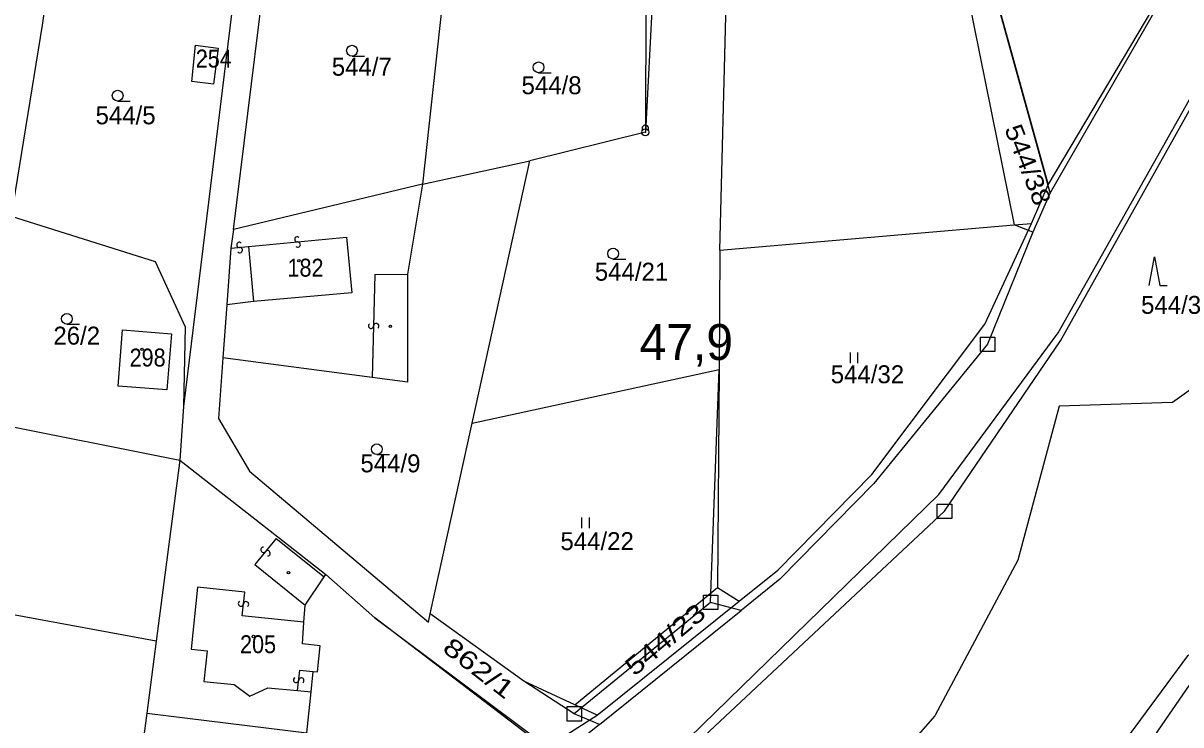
# Model space of a CAD drawing. Extents: x -680102 to -677253, y -1007548 to -1006096.
# Drawn here: x -679602.9 to -679441.7, y -1007197.5 to -1007099.8 of the extents above; entities that cross this region are included whole.
import ezdxf

# ---------------------------------------------------------------- set-up
doc = ezdxf.new("R2010")
doc.units = 0
for name, color, linetype, lineweight in [('1', 7, 'Continuous', 25), ('11', 7, 'Continuous', 25), ('24', 7, 'Continuous', 25), ('25', 7, 'Continuous', 25), ('35', 7, 'Continuous', 25), ('4', 7, 'Continuous', 25)]:
    doc.layers.add(name, color=color, linetype=linetype, lineweight=lineweight)
for name, color, linetype in [('18', 7, 'Continuous'), ('19', 7, 'Continuous'), ('56', 7, 'Continuous')]:
    doc.layers.add(name, color=color, linetype=linetype)

msp = doc.modelspace()

# ---------------------------------------------------------------- linework, layer by layer
at = {"layer": '1'}
for p, q in [((-679481.69, -1007044.65), (-679460.12, -1007122.3)), ((-679480.26, -1007051.71), (-679464.89, -1007127.87)), ((-679513.91, -1007069.87), (-679516.26, -1007114.97)), ((-679573.64, -1007128.49), (-679567.53, -1007078.91)), ((-679598.74, -1007089.06), (-679600.32, -1007100.05)), ((-679516.18, -1007095.82), (-679516.26, -1007114.97)), ((-679516.26, -1007114.97), (-679532.37, -1007118.94)), ((-679547.29, -1007122.2), (-679573.64, -1007128.49)), ((-679547.29, -1007122.2), (-679549.42, -1007134.75)), ((-679462.47, -1007127.66), (-679460.12, -1007122.3)), ((-679505.88, -1007131.4), (-679464.89, -1007127.87)), ((-679468.98, -1007141.69), (-679462.47, -1007127.66)), ((-679464.89, -1007127.87), (-679462.47, -1007127.66)), ((-679573.64, -1007128.49), (-679574.02, -1007131.12)), ((-679549.42, -1007134.75), (-679549.42, -1007149.76)), ((-679575.13, -1007146.4), (-679575.75, -1007154.83)), ((-679554.3, -1007149.14), (-679575.13, -1007146.4)), ((-679540.4, -1007155.5), (-679505.99, -1007148.01)), ((-679549.42, -1007149.76), (-679554.3, -1007149.14)), ((-679580.62, -1007153.16), (-679581.1, -1007160.64)), ((-679581.1, -1007160.64), (-679584.41, -1007185.88)), ((-679513.88, -1007202.94), (-679475.39, -1007165.44)), ((-679526.07, -1007194.74), (-679506.19, -1007178.41)), ((-679506.19, -1007178.41), (-679503.21, -1007180.3)), ((-679563.84, -1007183.24), (-679563.68, -1007180.84)), ((-679553.95, -1007182.63), (-679529.88, -1007200.6)), ((-679546.49, -1007183.2), (-679546.24, -1007182.06)), ((-679533.18, -1007191.45), (-679546.24, -1007182.06)), ((-679564.03, -1007186.25), (-679563.84, -1007183.24)), ((-679562.84, -1007192.91), (-679562.55, -1007190.09)), ((-679563.43, -1007198.62), (-679562.84, -1007192.91)), ((-679585.73, -1007195.92), (-679563.43, -1007198.62)), ((-679529.88, -1007200.6), (-679522.98, -1007196.16)), ((-679475.92, -1007196.29), (-679485.49, -1007207.11))]:
    msp.add_line(p, q, dxfattribs=at)
for points in [[(-679475.39, -1007165.44), (-679458.72, -1007142.92), (-679428.63, -1007089.4), (-679414.61, -1007067.19), (-679392.8, -1007041.16), (-679383.74, -1007034.41), (-679364.39, -1007022.5), (-679354.81, -1007027.12), (-679350.01, -1007026.23)], [(-679281.81, -1007027.69), (-679288.12, -1007026.06), (-679300.13, -1007025.55), (-679317.23, -1007033.9), (-679328.22, -1007036.44), (-679338.3, -1007036.24), (-679352.63, -1007045.79), (-679380.01, -1007071.86), (-679387.43, -1007092.29), (-679392.71, -1007125.35), (-679397.19, -1007140.32), (-679410.92, -1007159.43), (-679421.1, -1007177.36), (-679440.73, -1007187.9), (-679453.05, -1007204.6)], [(-679392.8, -1007041.16), (-679411.69, -1007075.81), (-679414.58, -1007097.41), (-679422.73, -1007127.1), (-679431.91, -1007144.79), (-679442.79, -1007152.62), (-679458.6, -1007153.13), (-679464.38, -1007174.57), (-679475.92, -1007196.29)], [(-679460.12, -1007122.3), (-679434.03, -1007078.35), (-679414.32, -1007049.92)], [(-679505.88, -1007131.4), (-679504.18, -1007064.29), (-679504.16, -1007063.4)], [(-679598.74, -1007089.06), (-679586.13, -1007086.43), (-679571.74, -1007080.61), (-679580.62, -1007153.16)], [(-679544.6, -1007097.51), (-679547.29, -1007122.2), (-679532.37, -1007118.94)], [(-679600.32, -1007100.05), (-679604.63, -1007126.67), (-679584.56, -1007132.96)], [(-679546.24, -1007182.06), (-679540.4, -1007155.5), (-679532.37, -1007118.94)], [(-679574.02, -1007131.12), (-679574.59, -1007139.02), (-679575.13, -1007146.4)], [(-679584.56, -1007132.96), (-679580.37, -1007142.08), (-679580.62, -1007153.16)], [(-679505.88, -1007131.4), (-679505.99, -1007148.01), (-679506.19, -1007178.41)], [(-679497.82, -1007175.98), (-679484.69, -1007162.65), (-679468.98, -1007141.69)], [(-679625.08, -1007151.88), (-679607.2, -1007155.44), (-679581.1, -1007160.64)], [(-679575.75, -1007154.83), (-679571.4, -1007162.2), (-679546.49, -1007183.2)], [(-679581.1, -1007160.64), (-679567.45, -1007171.33), (-679560.77, -1007176.57)], [(-679584.41, -1007185.88), (-679649.73, -1007173.85), (-679650.7, -1007173.67)], [(-679522.98, -1007196.16), (-679503.21, -1007180.3), (-679497.82, -1007175.98)], [(-679563.68, -1007180.84), (-679561.01, -1007176.92), (-679560.77, -1007176.57), (-679553.95, -1007182.63)], [(-679455.65, -1007214.04), (-679449.69, -1007205.42), (-679438.39, -1007189.02), (-679418.03, -1007179.85)], [(-679584.41, -1007185.88), (-679585.73, -1007195.92), (-679588.44, -1007216.55)], [(-679562.55, -1007190.09), (-679561.96, -1007190.15), (-679561.58, -1007186.51), (-679564.03, -1007186.25)], [(-679522.98, -1007196.16), (-679526.07, -1007194.74), (-679533.18, -1007191.45)]]:
    msp.add_lwpolyline(points, dxfattribs=at)
for points in [[(-679578.95, -1007102.81), (-679575.8, -1007103.23), (-679576.41, -1007108.27), (-679579.47, -1007107.9)], [(-679589.1, -1007142.48), (-679582.28, -1007143.04), (-679582.91, -1007150.84), (-679589.73, -1007150.32)]]:
    msp.add_lwpolyline(points, close=True, dxfattribs=at)
at = {"layer": '11'}
for p, q in [((-679459.84, -1007123.39), (-679462.28, -1007128.86)), ((-679462.28, -1007128.86), (-679464.89, -1007127.87)), ((-679507.16, -1007180.47), (-679505.99, -1007148.01)), ((-679474.58, -1007167.77), (-679513.45, -1007204.14)), ((-679522.66, -1007197.48), (-679502.92, -1007181.58)), ((-679522.66, -1007197.48), (-679526.16, -1007195.99))]:
    msp.add_line(p, q, dxfattribs=at)
for points in [[(-679433.94, -1007078.32), (-679459.84, -1007123.39), (-679481.69, -1007044.65)], [(-679474.58, -1007167.77), (-679458.4, -1007144.01), (-679428.52, -1007090.53)], [(-679462.28, -1007128.86), (-679468.57, -1007144.5), (-679484.43, -1007163.89)], [(-679484.43, -1007163.89), (-679497.54, -1007177.25), (-679502.92, -1007181.58)], [(-679502.92, -1007181.58), (-679507.16, -1007180.47), (-679526.16, -1007195.99), (-679533.18, -1007191.45)], [(-679522.66, -1007197.48), (-679528.41, -1007202.14), (-679553.95, -1007182.63)]]:
    msp.add_lwpolyline(points, dxfattribs=at)
at = {"layer": '24'}
for radius in [0.5, 0.022]:
    msp.add_circle((-679516.26, -1007114.97), radius, dxfattribs=at)
msp.add_arc((-679516.261, -1007114.407), 0.437, 328.35109, 209.97456, dxfattribs=at)
at = {"layer": '25'}
for p, q in [((-679557.13, -1007104.35), (-679555.38, -1007104.35)), ((-679531.14, -1007106.66), (-679529.39, -1007106.66)), ((-679589.78, -1007110.61), (-679588.03, -1007110.61)), ((-679520.75, -1007132.62), (-679519, -1007132.62)), ((-679596.86, -1007141.71), (-679595.11, -1007141.71)), ((-679487.687, -1007147.145), (-679487.687, -1007145.645)), ((-679486.653, -1007147.145), (-679486.653, -1007145.645)), ((-679553.67, -1007159.87), (-679551.92, -1007159.87)), ((-679525.087, -1007170.125), (-679525.087, -1007168.625)), ((-679524.053, -1007170.125), (-679524.053, -1007168.625))]:
    msp.add_line(p, q, dxfattribs=at)
msp.add_lwpolyline([(-679446.07, -1007136.31), (-679445.32, -1007132.31), (-679444.57, -1007136.31), (-679443.57, -1007136.31)], dxfattribs=at)
for centre, radius in [((-679557.13, -1007103.6), 0.75), ((-679577.549, -1007104.4), 0.122), ((-679531.14, -1007105.91), 0.75), ((-679589.78, -1007109.86), 0.75), ((-679520.75, -1007131.87), 0.75), ((-679564.53, -1007132.85), 0.175), ((-679596.86, -1007140.96), 0.75), ((-679551.79, -1007142), 0.175), ((-679586.39, -1007145.21), 0.175), ((-679553.67, -1007159.12), 0.75), ((-679565.98, -1007176.32), 0.175), ((-679570.85, -1007185.22), 0.175)]:
    msp.add_circle(centre, radius, dxfattribs=at)
for centre, radius, start, end in [((-679564.751, -1007129.884), 0.367, 42.71022, 274.84355), ((-679572.821, -1007130.644), 0.367, 42.71022, 274.84355), ((-679572.76, -1007131.377), 0.368, 222.79917, 94.83656), ((-679564.69, -1007130.617), 0.368, 222.79917, 94.83656), ((-679554.488, -1007141.935), 0.368, 125.93681, 357.66872), ((-679553.753, -1007141.963), 0.368, 305.3913, 177.97271), ((-679569.463, -1007173.143), 0.369, 87.97751, 319.80247), ((-679568.897, -1007173.615), 0.368, 267.50155, 140.29526), ((-679572.615, -1007180.639), 0.367, 121.47976, 353.59371), ((-679571.884, -1007180.722), 0.369, 301.3657, 173.60843), ((-679564.925, -1007191.268), 0.368, 121.51241, 353.43874), ((-679564.194, -1007191.354), 0.369, 301.23289, 173.53502)]:
    msp.add_arc(centre, radius, start, end, dxfattribs=at)
at = {"layer": '35'}
for points in [[(-679469.57, -1007143.5), (-679467.57, -1007143.5), (-679467.57, -1007145.5), (-679469.57, -1007145.5)], [(-679475.58, -1007166.77), (-679473.58, -1007166.77), (-679473.58, -1007168.77), (-679475.58, -1007168.77)], [(-679508.16, -1007179.47), (-679506.16, -1007179.47), (-679506.16, -1007181.47), (-679508.16, -1007181.47)], [(-679527.16, -1007194.99), (-679525.16, -1007194.99), (-679525.16, -1007196.99), (-679527.16, -1007196.99)]]:
    msp.add_lwpolyline(points, close=True, dxfattribs=at)
at = {"layer": '4'}
for p, q in [((-679571.56, -1007130.89), (-679570.86, -1007138.56)), ((-679553.94, -1007134.76), (-679554.3, -1007149.14)), ((-679553.94, -1007134.76), (-679549.42, -1007134.75)), ((-679570.86, -1007138.56), (-679574.59, -1007139.02)), ((-679567.7, -1007171.56), (-679561.01, -1007176.92)), ((-679563.84, -1007183.24), (-679572.42, -1007182.34))]:
    msp.add_line(p, q, dxfattribs=at)
for points in [[(-679574.02, -1007131.12), (-679571.56, -1007130.89), (-679557.89, -1007129.6), (-679557.16, -1007137.34), (-679570.86, -1007138.56)], [(-679567.7, -1007171.56), (-679570.66, -1007175.19), (-679563.68, -1007180.84)], [(-679572.42, -1007182.34), (-679572.08, -1007179.02), (-679578.65, -1007178.35), (-679579.54, -1007187), (-679577.33, -1007187.23), (-679577.77, -1007191.48), (-679573.57, -1007191.91)], [(-679564.71, -1007192.72), (-679564.41, -1007189.89), (-679562.55, -1007190.09)], [(-679573.57, -1007191.91), (-679571.36, -1007193.55), (-679568.87, -1007192.39)], [(-679568.87, -1007192.39), (-679564.71, -1007192.72), (-679562.84, -1007192.91)]]:
    msp.add_lwpolyline(points, dxfattribs=at)

# ---------------------------------------------------------------- texts
at = {"layer": '18'}
for s, p in [('544/7', (-679559.95, -1007107.08)), ('544/8', (-679533.51, -1007109.66)), ('544/5', (-679592.86, -1007113.85)), ('544/21', (-679523.3, -1007135.64)), ('544/3', (-679447.19, -1007140.26)), ('26/2', (-679598.74, -1007144.55)), ('544/32', (-679490.43, -1007149.93)), ('544/9', (-679555.96, -1007162.34)), ('544/22', (-679528.09, -1007173.18))]:
    msp.add_text(s, height=2.5, dxfattribs=at).set_placement(p)
for s, rotation, width, p in [('544/38', 291.402, 1.15, (-679466.271, -1007114.473)), ('544/23', 39.9, 1.3, (-679517.795, -1007190.849)), ('862/1', 322.303, 1.35, (-679544.7, -1007187.155))]:
    msp.add_text(s, height=2.5, rotation=rotation, dxfattribs=dict(at, width=width)).set_placement(p)
at = {"layer": '19', "width": 0.9}
for s, p in [('254', (-679578.9, -1007105.94)), ('182', (-679566.12, -1007135.08)), ('298', (-679588.12, -1007147.6)), ('205', (-679572.73, -1007187.54))]:
    msp.add_text(s, height=2.5, dxfattribs=at).set_placement(p)
at = {"layer": '56'}
msp.add_text('47,9', height=5, dxfattribs=at).set_placement((-679517.06, -1007146.69))

doc.saveas('drawing.dxf')
